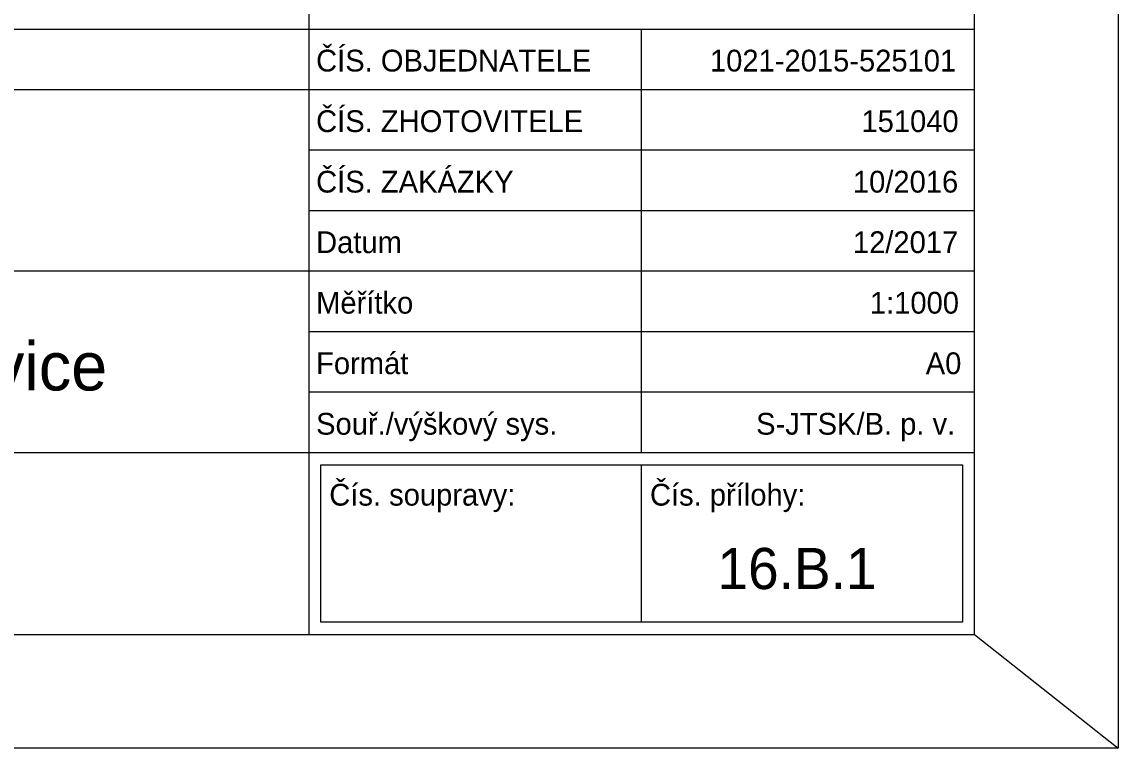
# Model space of a CAD drawing. Extents: x -574342 to -507939, y -1144044 to -1123894.
# Drawn here: x -508117.3 to -508026.8, y -1144035.7 to -1143975.7 of the extents above; entities that cross this region are included whole.
import ezdxf

# ---------------------------------------------------------------- set-up
doc = ezdxf.new("R2010")
doc.units = 0
for name, color, linetype in [('Level 1', 7, 'Continuous'), ('Level 255', 7, 'Continuous'), ('rozpiska', 7, 'Continuous')]:
    doc.layers.add(name, color=color, linetype=linetype)

msp = doc.modelspace()

# ---------------------------------------------------------------- linework, layer by layer
at = {"layer": 'Level 1'}
msp.add_line((-508038.629, -1144026.312), (-508026.763, -1144035.7), dxfattribs=at)
msp.add_lwpolyline([(-508026.763, -1142847.7), (-508026.763, -1144035.7), (-508866.763, -1144035.7), (-508866.763, -1142847.7)], close=True, dxfattribs=at)
msp.add_lwpolyline([(-508057.922, -1144035.7), (-508111.734, -1144035.7)], dxfattribs=at)
at = {"layer": 'Level 255'}
msp.add_line((-508228.598, -1144026.312), (-508038.629, -1144026.312), dxfattribs=at)
msp.add_line((-508228.598, -1144026.312), (-508038.629, -1144026.312), dxfattribs=at)
msp.add_line((-508228.598, -1144026.312), (-508038.629, -1144026.312), dxfattribs=at)
msp.add_line((-508228.598, -1144026.312), (-508038.629, -1144026.312), dxfattribs=at)
at = {"layer": 'rozpiska'}
for p, q in [((-508093.629, -1143946.313), (-508093.629, -1144026.312)), ((-508038.629, -1144026.312), (-508038.629, -1143946.313)), ((-508038.629, -1144026.312), (-508038.629, -1143946.594)), ((-508228.627, -1143976.313), (-508038.629, -1143976.313)), ((-508066.129, -1144011.313), (-508066.129, -1143976.313)), ((-508038.629, -1143981.313), (-508228.627, -1143981.313)), ((-508038.629, -1143986.313), (-508093.629, -1143986.313)), ((-508038.629, -1143991.313), (-508093.629, -1143991.313)), ((-508038.629, -1143996.313), (-508228.627, -1143996.313)), ((-508038.629, -1144001.313), (-508093.629, -1144001.313)), ((-508038.629, -1144006.313), (-508093.629, -1144006.313)), ((-508038.629, -1144011.313), (-508228.627, -1144011.313)), ((-508066.129, -1144025.313), (-508066.129, -1144012.313)), ((-508228.627, -1144026.312), (-508038.629, -1144026.312)), ((-508228.627, -1144026.312), (-508038.629, -1144026.312))]:
    msp.add_line(p, q, dxfattribs=at)
msp.add_lwpolyline([(-508092.629, -1144012.313), (-508039.629, -1144012.313), (-508039.629, -1144025.313), (-508092.629, -1144025.313)], close=True, dxfattribs=at)

# ---------------------------------------------------------------- texts
for s, height, p in [('ČÍS. OBJEDNATELE', 1.8, (-508093.028, -1143979.813)), ('1021-2015-525101', 1.8, (-508060.484, -1143979.814)), ('ČÍS. ZHOTOVITELE', 1.8, (-508093.028, -1143984.813)), ('151040', 1.8, (-508047.968, -1143984.814)), ('ČÍS. ZAKÁZKY', 1.8, (-508093.028, -1143989.813)), ('10/2016', 1.8, (-508048.673, -1143989.814)), ('Datum', 1.8, (-508093.028, -1143994.813)), ('12/2017', 1.8, (-508048.673, -1143994.814)), ('Měřítko', 1.8, (-508093.028, -1143999.813)), ('1:1000', 1.8, (-508047.268, -1143999.814)), ('Komplexní pozemkové úpravy v k.ú. Kunovice', 3.99996, (-508219.698, -1144006.161)), ('Formát', 1.8, (-508093.028, -1144004.813)), ('A0', 1.8, (-508042.655, -1144004.814)), ('Souř./výškový sys.', 1.8, (-508093.028, -1144009.813)), ('S-JTSK/B. p. v.', 1.8, (-508056.67, -1144009.814)), ('Čís. soupravy:', 1.8, (-508091.942, -1144015.671)), ('Čís. přílohy:', 1.8, (-508065.442, -1144015.671)), ('16.B.1', 3.4, (-508059.865, -1144022.566))]:
    msp.add_text(s, height=height, dxfattribs=at).set_placement(p)

doc.saveas('drawing.dxf')
